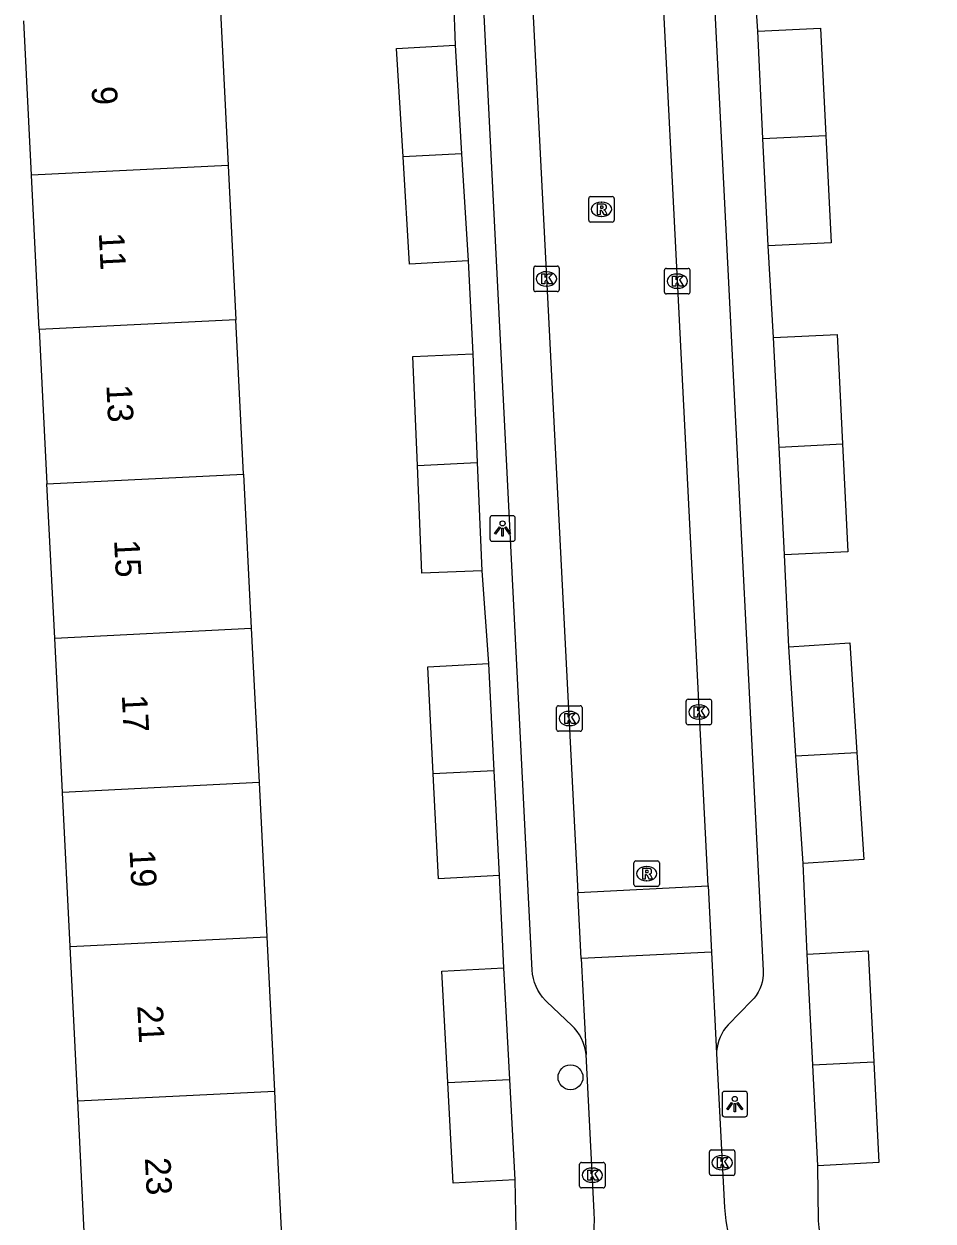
# Model space of a CAD drawing. Extents: x 161084 to 161928, y 385355 to 386522.
# Drawn here: x 161437.71 to 161473.38, y 385662.25 to 385709.2 of the extents above; entities that cross this region are included whole.
import ezdxf

# ---------------------------------------------------------------- set-up
doc = ezdxf.new("R2010")
doc.units = 0
for name, color, linetype in [('IMGEO_Boom', 7, 'Continuous'), ('IMGEO_Kolk', 7, 'Continuous'), ('IMGEO_Lichtpunt', 7, 'Continuous'), ('IMGEO_Pand', 7, 'Continuous'), ('IMGEO_Pand_nummerreeks', 7, 'Continuous'), ('IMGEO_Rijbaan_lokaal_open', 7, 'Continuous'), ('IMGEO_Rioolput', 7, 'Continuous'), ('IMGEO_Voetpad_open', 7, 'Continuous')]:
    doc.layers.add(name, color=color, linetype=linetype)

msp = doc.modelspace()

# ---------------------------------------------------------------- linework, layer by layer
at = {"layer": 'IMGEO_Boom'}
msp.add_circle((161459.156, 385667.888), 0.489, dxfattribs=at)
at = {"layer": 'IMGEO_Kolk'}
for p, q in [((161457.711, 385698.777), (161457.711, 385699.629)), ((161457.786, 385699.703), (161458.638, 385699.703)), ((161458.199, 385699.483), (161458.224, 385699.483)), ((161458.712, 385699.629), (161458.712, 385698.777)), ((161462.843, 385698.687), (161462.843, 385699.539)), ((161462.918, 385699.613), (161463.77, 385699.613)), ((161463.331, 385699.393), (161463.356, 385699.393)), ((161463.844, 385699.539), (161463.844, 385698.687)), ((161458.222, 385698.923), (161458.197, 385698.923)), ((161463.354, 385698.833), (161463.329, 385698.833)), ((161458.638, 385698.703), (161457.786, 385698.703)), ((161463.77, 385698.613), (161462.918, 385698.613)), ((161458.606, 385681.534), (161458.606, 385682.386)), ((161458.681, 385682.46), (161459.533, 385682.46)), ((161459.607, 385682.386), (161459.607, 385681.534)), ((161463.693, 385681.79), (161463.693, 385682.642)), ((161463.768, 385682.716), (161464.62, 385682.716)), ((161464.181, 385682.496), (161464.206, 385682.496)), ((161464.694, 385682.642), (161464.694, 385681.79)), ((161459.094, 385682.24), (161459.119, 385682.24)), ((161464.204, 385681.936), (161464.179, 385681.936)), ((161459.533, 385681.46), (161458.681, 385681.46)), ((161459.117, 385681.68), (161459.092, 385681.68)), ((161464.62, 385681.716), (161463.768, 385681.716)), ((161464.681, 385665.041), (161465.533, 385665.041)), ((161459.587, 385664.549), (161460.439, 385664.549)), ((161464.606, 385664.115), (161464.606, 385664.967)), ((161465.094, 385664.821), (161465.119, 385664.821)), ((161465.607, 385664.967), (161465.607, 385664.115)), ((161459.512, 385663.623), (161459.512, 385664.475)), ((161460, 385664.329), (161460.025, 385664.329)), ((161460.513, 385664.475), (161460.513, 385663.623)), ((161465.533, 385664.041), (161464.681, 385664.041)), ((161465.117, 385664.261), (161465.092, 385664.261)), ((161460.023, 385663.769), (161459.998, 385663.769)), ((161460.439, 385663.549), (161459.587, 385663.549))]:
    msp.add_line(p, q, dxfattribs=at)
for points in [[(161457.711, 385698.777), (161457.711, 385699.629)], [(161457.786, 385699.703), (161458.638, 385699.703)], [(161458.032, 385699.403), (161458.155, 385699.403), (161458.155, 385699.252), (161458.285, 385699.403), (161458.449, 385699.403), (161458.303, 385699.252), (161458.456, 385699.003), (161458.304, 385699.003), (161458.219, 385699.167), (161458.155, 385699.1), (161458.155, 385699.003), (161458.032, 385699.003), (161458.032, 385699.403)], [(161458.712, 385699.629), (161458.712, 385698.777)], [(161462.843, 385698.687), (161462.843, 385699.539)], [(161462.918, 385699.613), (161463.77, 385699.613)], [(161463.164, 385699.313), (161463.287, 385699.313), (161463.287, 385699.162), (161463.417, 385699.313), (161463.581, 385699.313), (161463.435, 385699.162), (161463.588, 385698.913), (161463.436, 385698.913), (161463.351, 385699.077), (161463.287, 385699.01), (161463.287, 385698.913), (161463.164, 385698.913), (161463.164, 385699.313)], [(161463.844, 385699.539), (161463.844, 385698.687)], [(161458.638, 385698.703), (161457.786, 385698.703)], [(161463.77, 385698.613), (161462.918, 385698.613)], [(161458.606, 385681.534), (161458.606, 385682.386)], [(161458.681, 385682.46), (161459.533, 385682.46)], [(161459.607, 385682.386), (161459.607, 385681.534)], [(161463.693, 385681.79), (161463.693, 385682.642)], [(161463.768, 385682.716), (161464.62, 385682.716)], [(161464.014, 385682.416), (161464.137, 385682.416), (161464.137, 385682.265), (161464.267, 385682.416), (161464.431, 385682.416), (161464.285, 385682.265), (161464.438, 385682.016), (161464.286, 385682.016), (161464.201, 385682.18), (161464.137, 385682.113), (161464.137, 385682.016), (161464.014, 385682.016), (161464.014, 385682.416)], [(161464.694, 385682.642), (161464.694, 385681.79)], [(161458.927, 385682.16), (161459.05, 385682.16), (161459.05, 385682.009), (161459.18, 385682.16), (161459.344, 385682.16), (161459.198, 385682.009), (161459.351, 385681.76), (161459.199, 385681.76), (161459.114, 385681.924), (161459.05, 385681.857), (161459.05, 385681.76), (161458.927, 385681.76), (161458.927, 385682.16)], [(161459.533, 385681.46), (161458.681, 385681.46)], [(161464.62, 385681.716), (161463.768, 385681.716)], [(161464.681, 385665.041), (161465.533, 385665.041)], [(161459.587, 385664.549), (161460.439, 385664.549)], [(161464.606, 385664.115), (161464.606, 385664.967)], [(161464.927, 385664.741), (161465.05, 385664.741), (161465.05, 385664.59), (161465.18, 385664.741), (161465.344, 385664.741), (161465.198, 385664.59), (161465.351, 385664.341), (161465.199, 385664.341), (161465.114, 385664.505), (161465.05, 385664.438), (161465.05, 385664.341), (161464.927, 385664.341), (161464.927, 385664.741)], [(161465.607, 385664.967), (161465.607, 385664.115)], [(161459.512, 385663.623), (161459.512, 385664.475)], [(161459.833, 385664.249), (161459.956, 385664.249), (161459.956, 385664.098), (161460.086, 385664.249), (161460.25, 385664.249), (161460.104, 385664.098), (161460.257, 385663.849), (161460.105, 385663.849), (161460.02, 385664.013), (161459.956, 385663.946), (161459.956, 385663.849), (161459.833, 385663.849), (161459.833, 385664.249)], [(161460.513, 385664.475), (161460.513, 385663.623)], [(161465.533, 385664.041), (161464.681, 385664.041)], [(161460.439, 385663.549), (161459.587, 385663.549)]]:
    msp.add_lwpolyline(points, dxfattribs=at)
for centre, start, end in [((161457.788, 385699.627), 91.552, 178.448), ((161457.788, 385699.627), 91.552, 178.448), ((161458.636, 385699.627), 1.552, 88.448), ((161458.636, 385699.627), 1.552, 88.448), ((161462.92, 385699.537), 91.552, 178.448), ((161462.92, 385699.537), 91.552, 178.448), ((161463.768, 385699.537), 1.552, 88.448), ((161463.768, 385699.537), 1.552, 88.448), ((161457.788, 385698.779), 181.552, 268.448), ((161457.788, 385698.779), 181.552, 268.448), ((161458.636, 385698.779), 271.552, 358.448), ((161458.636, 385698.779), 271.552, 358.448), ((161462.92, 385698.689), 181.552, 268.448), ((161462.92, 385698.689), 181.552, 268.448), ((161463.768, 385698.689), 271.552, 358.448), ((161463.768, 385698.689), 271.552, 358.448), ((161458.683, 385682.384), 91.552, 178.448), ((161458.683, 385682.384), 91.552, 178.448), ((161459.531, 385682.384), 1.552, 88.448), ((161459.531, 385682.384), 1.552, 88.448), ((161463.77, 385682.64), 91.552, 178.448), ((161463.77, 385682.64), 91.552, 178.448), ((161464.618, 385682.64), 1.552, 88.448), ((161464.618, 385682.64), 1.552, 88.448), ((161458.683, 385681.536), 181.552, 268.448), ((161458.683, 385681.536), 181.552, 268.448), ((161459.531, 385681.536), 271.552, 358.448), ((161459.531, 385681.536), 271.552, 358.448), ((161463.77, 385681.792), 181.552, 268.448), ((161463.77, 385681.792), 181.552, 268.448), ((161464.618, 385681.792), 271.552, 358.448), ((161464.618, 385681.792), 271.552, 358.448), ((161464.683, 385664.965), 91.552, 178.448), ((161464.683, 385664.965), 91.552, 178.448), ((161465.531, 385664.965), 1.552, 88.448), ((161465.531, 385664.965), 1.552, 88.448), ((161459.589, 385664.473), 91.552, 178.448), ((161459.589, 385664.473), 91.552, 178.448), ((161460.437, 385664.473), 1.552, 88.448), ((161460.437, 385664.473), 1.552, 88.448), ((161464.683, 385664.117), 181.552, 268.448), ((161464.683, 385664.117), 181.552, 268.448), ((161465.531, 385664.117), 271.552, 358.448), ((161465.531, 385664.117), 271.552, 358.448), ((161459.589, 385663.625), 181.552, 268.448), ((161459.589, 385663.625), 181.552, 268.448), ((161460.437, 385663.625), 271.552, 358.448), ((161460.437, 385663.625), 271.552, 358.448)]:
    msp.add_arc(centre, 0.0765, start, end, dxfattribs=at)
for centre, major_axis, ratio, start_param, end_param in [((161458.198, 385699.203), (-0.387, 0.002), 0.722429, 4.712389, 7.853982), ((161458.223, 385699.203), (-0.39, 0.002), 0.717154, 1.570796, 4.712389), ((161463.33, 385699.113), (-0.387, 0.002), 0.722429, 4.712389, 7.853982), ((161463.355, 385699.113), (-0.39, 0.002), 0.717154, 1.570796, 4.712389), ((161464.18, 385682.216), (-0.387, 0.002), 0.722429, 4.712389, 7.853982), ((161464.205, 385682.216), (-0.39, 0.002), 0.717154, 1.570796, 4.712389), ((161459.093, 385681.96), (-0.387, 0.002), 0.722429, 4.712389, 7.853982), ((161459.118, 385681.96), (-0.39, 0.002), 0.717154, 1.570796, 4.712389), ((161465.093, 385664.541), (-0.387, 0.002), 0.722429, 4.712389, 7.853982), ((161465.118, 385664.541), (-0.39, 0.002), 0.717154, 1.570796, 4.712389), ((161459.999, 385664.049), (-0.387, 0.002), 0.722429, 4.712389, 7.853982), ((161460.024, 385664.049), (-0.39, 0.002), 0.717154, 1.570796, 4.712389)]:
    msp.add_ellipse(centre, major_axis=major_axis, ratio=ratio, start_param=start_param, end_param=end_param, dxfattribs=at)
at = {"layer": 'IMGEO_Lichtpunt'}
for p, q in [((161456.893, 385689.911), (161456.085, 385689.911)), ((161456.893, 385689.911), (161456.085, 385689.911)), ((161455.991, 385689.816), (161455.991, 385689.009)), ((161455.991, 385689.816), (161455.991, 385689.009)), ((161456.987, 385689.009), (161456.987, 385689.816)), ((161456.987, 385689.009), (161456.987, 385689.816)), ((161456.085, 385688.915), (161456.893, 385688.915)), ((161456.085, 385688.915), (161456.893, 385688.915)), ((161466.004, 385667.337), (161465.196, 385667.337)), ((161466.004, 385667.337), (161465.196, 385667.337)), ((161465.102, 385667.242), (161465.102, 385666.435)), ((161465.102, 385667.242), (161465.102, 385666.435)), ((161466.098, 385666.435), (161466.098, 385667.242)), ((161466.098, 385666.435), (161466.098, 385667.242)), ((161465.196, 385666.341), (161466.004, 385666.341)), ((161465.196, 385666.341), (161466.004, 385666.341))]:
    msp.add_line(p, q, dxfattribs=at)
for points in [[(161456.365, 385689.48), (161456.404, 385689.452), (161456.216, 385689.19), (161456.178, 385689.217), (161456.365, 385689.48)], [(161456.467, 385689.432), (161456.514, 385689.432), (161456.514, 385689.11), (161456.467, 385689.11), (161456.467, 385689.432)], [(161456.577, 385689.452), (161456.615, 385689.479), (161456.802, 385689.217), (161456.763, 385689.189), (161456.577, 385689.452)], [(161465.476, 385666.906), (161465.515, 385666.878), (161465.327, 385666.616), (161465.289, 385666.643), (161465.476, 385666.906)], [(161465.578, 385666.858), (161465.625, 385666.858), (161465.625, 385666.536), (161465.578, 385666.536), (161465.578, 385666.858)], [(161465.688, 385666.878), (161465.726, 385666.905), (161465.913, 385666.643), (161465.874, 385666.615), (161465.688, 385666.878)]]:
    msp.add_lwpolyline(points, dxfattribs=at)
for centre in [(161456.49, 385689.614), (161465.601, 385667.04)]:
    msp.add_circle(centre, 0.0994, dxfattribs=at)
for centre, start, end in [((161456.085, 385689.816), 90, 180), ((161456.085, 385689.816), 90, 180), ((161456.893, 385689.816), 0, 90), ((161456.893, 385689.816), 0, 90), ((161456.085, 385689.009), 180, 270), ((161456.085, 385689.009), 180, 270), ((161456.893, 385689.009), 270, 0), ((161456.893, 385689.009), 270, 360), ((161465.196, 385667.242), 90, 180), ((161465.196, 385667.242), 90, 180), ((161466.004, 385667.242), 0, 90), ((161466.004, 385667.242), 0, 90), ((161465.196, 385666.435), 180, 270), ((161465.196, 385666.435), 180, 270), ((161466.004, 385666.435), 270, 0), ((161466.004, 385666.435), 270, 360)]:
    msp.add_arc(centre, 0.0946, start, end, dxfattribs=at)
at = {"layer": 'IMGEO_Pand'}
for points in [[(161445.425, 385709.704), (161445.727, 385703.653)], [(161438.012, 385703.269), (161437.711, 385709.32)], [(161466.502, 385708.921), (161468.969, 385709.041), (161469.174, 385704.83)], [(161466.707, 385704.704), (161466.502, 385708.921)], [(161452.585, 385703.994), (161452.333, 385708.233), (161454.631, 385708.369)], [(161454.631, 385708.369), (161454.884, 385704.109)], [(161466.707, 385704.704), (161469.174, 385704.83)], [(161466.912, 385700.497), (161466.707, 385704.704)], [(161469.174, 385704.83), (161469.379, 385700.617), (161466.912, 385700.497)], [(161454.884, 385704.109), (161452.585, 385703.994)], [(161455.134, 385699.91), (161452.836, 385699.774), (161452.585, 385703.994)], [(161454.884, 385704.109), (161455.134, 385699.91)], [(161445.727, 385703.653), (161438.012, 385703.269)], [(161445.727, 385703.653), (161446.029, 385697.602)], [(161438.314, 385697.218), (161438.012, 385703.269)], [(161446.029, 385697.602), (161438.314, 385697.218)], [(161446.331, 385691.55), (161446.029, 385697.602)], [(161438.314, 385697.218), (161438.616, 385691.166)], [(161467.126, 385696.903), (161469.617, 385697.026), (161469.83, 385692.727)], [(161467.339, 385692.6), (161467.126, 385696.903)], [(161453.147, 385691.889), (161452.97, 385696.164), (161455.322, 385696.261)], [(161455.322, 385696.261), (161455.498, 385692.006)], [(161467.339, 385692.6), (161469.83, 385692.727)], [(161469.83, 385692.727), (161470.039, 385688.5), (161467.548, 385688.377)], [(161467.548, 385688.377), (161467.339, 385692.6)], [(161453.147, 385691.889), (161455.498, 385692.006)], [(161455.674, 385687.755), (161453.322, 385687.658), (161453.147, 385691.889)], [(161455.498, 385692.006), (161455.674, 385687.755)], [(161438.616, 385691.166), (161446.331, 385691.55)], [(161446.331, 385691.55), (161446.632, 385685.499)], [(161438.917, 385685.115), (161438.616, 385691.166)], [(161438.917, 385685.115), (161446.632, 385685.499)], [(161446.632, 385685.499), (161446.934, 385679.447)], [(161439.219, 385679.063), (161438.917, 385685.115)], [(161467.724, 385684.765), (161470.114, 385684.922), (161470.396, 385680.623)], [(161468.003, 385680.501), (161467.724, 385684.765)], [(161453.767, 385679.787), (161453.555, 385683.992), (161455.934, 385684.112)], [(161455.934, 385684.112), (161456.146, 385679.906)], [(161468.003, 385680.501), (161470.396, 385680.623)], [(161468.279, 385676.277), (161468.003, 385680.501)], [(161470.396, 385680.623), (161470.67, 385676.433), (161468.279, 385676.277)], [(161456.146, 385679.906), (161453.767, 385679.787)], [(161456.353, 385675.798), (161453.974, 385675.678), (161453.767, 385679.787)], [(161456.146, 385679.906), (161456.353, 385675.798)], [(161446.934, 385679.447), (161439.219, 385679.063)], [(161439.521, 385673.012), (161439.219, 385679.063)], [(161446.934, 385679.447), (161447.236, 385673.396)], [(161439.521, 385673.012), (161447.236, 385673.396)], [(161439.823, 385666.96), (161439.521, 385673.012)], [(161447.236, 385673.396), (161447.538, 385667.344)], [(161468.441, 385672.721), (161470.839, 385672.842), (161471.058, 385668.497)], [(161468.66, 385668.371), (161468.441, 385672.721)], [(161454.341, 385667.683), (161454.111, 385672.055), (161456.529, 385672.182)], [(161456.529, 385672.182), (161456.76, 385667.803)], [(161468.66, 385668.371), (161471.058, 385668.497)], [(161468.859, 385664.422), (161468.66, 385668.371)], [(161471.058, 385668.497), (161471.257, 385664.543), (161468.859, 385664.422)], [(161454.341, 385667.683), (161456.76, 385667.803)], [(161456.76, 385667.803), (161456.968, 385663.862)], [(161447.538, 385667.344), (161447.599, 385666.114), (161447.848, 385661.12), (161440.133, 385660.736), (161439.823, 385666.96)], [(161439.823, 385666.96), (161447.538, 385667.344)], [(161456.968, 385663.862), (161454.549, 385663.734), (161454.341, 385667.683)]]:
    msp.add_lwpolyline(points, dxfattribs=at)
at = {"layer": 'IMGEO_Rijbaan_lokaal_open'}
for points in [[(161464.554, 385675.399), (161461.556, 385734.509)], [(161456.469, 385733.372), (161459.446, 385675.139)], [(161459.446, 385675.139), (161464.554, 385675.399)], [(161464.554, 385675.399), (161464.686, 385672.802)], [(161459.579, 385672.542), (161459.446, 385675.139)], [(161464.686, 385672.802), (161459.579, 385672.542)], [(161459.579, 385672.542), (161459.771, 385668.777)], [(161464.686, 385672.802), (161464.888, 385668.818)], [(161457.453, 385657.375), (161457.88, 385657.686), (161458.277, 385658.034), (161458.641, 385658.416), (161458.97, 385658.83), (161459.261, 385659.271), (161459.511, 385659.736), (161459.718, 385660.221), (161459.881, 385660.724), (161459.999, 385661.238), (161460.07, 385661.762), (161460.095, 385662.289), (161460.087, 385662.596), (161459.771, 385668.777)], [(161464.888, 385668.818), (161465.196, 385662.776), (161465.246, 385662.255), (161465.343, 385661.741), (161465.485, 385661.237), (161465.672, 385660.748), (161465.902, 385660.277), (161466.173, 385659.829), (161466.482, 385659.407), (161466.828, 385659.015), (161467.208, 385658.655), (161467.619, 385658.33), (161468.057, 385658.043), (161468.518, 385657.797), (161469, 385657.592), (161469.499, 385657.432), (161470.009, 385657.317), (161470.528, 385657.247), (161471.051, 385657.225), (161471.421, 385657.237), (161472.776, 385657.326)]]:
    msp.add_lwpolyline(points, dxfattribs=at)
at = {"layer": 'IMGEO_Rioolput'}
for p, q in [((161459.869, 385701.506), (161459.869, 385702.358)), ((161459.944, 385702.432), (161460.796, 385702.432)), ((161460.357, 385702.212), (161460.382, 385702.212)), ((161460.87, 385702.358), (161460.87, 385701.506)), ((161460.38, 385701.652), (161460.355, 385701.652)), ((161460.796, 385701.432), (161459.944, 385701.432)), ((161461.643, 385675.451), (161461.643, 385676.303)), ((161461.718, 385676.377), (161462.57, 385676.377)), ((161462.644, 385676.303), (161462.644, 385675.451)), ((161462.131, 385676.157), (161462.156, 385676.157)), ((161462.57, 385675.377), (161461.718, 385675.377)), ((161462.154, 385675.597), (161462.129, 385675.597))]:
    msp.add_line(p, q, dxfattribs=at)
for points in [[(161459.869, 385701.506), (161459.869, 385702.358)], [(161459.944, 385702.432), (161460.796, 385702.432)], [(161460.458, 385702.13), (161460.206, 385702.132), (161460.206, 385701.732)], [(161460.87, 385702.358), (161460.87, 385701.506)], [(161460.206, 385701.732), (161460.33, 385701.732), (161460.33, 385701.894), (161460.341, 385701.894)], [(161460.384, 385702.051), (161460.33, 385702.051), (161460.33, 385701.97)], [(161460.33, 385701.97), (161460.382, 385701.97)], [(161460.388, 385701.865), (161460.459, 385701.732), (161460.599, 385701.732), (161460.534, 385701.858)], [(161460.796, 385701.432), (161459.944, 385701.432)], [(161461.643, 385675.451), (161461.643, 385676.303)], [(161461.718, 385676.377), (161462.57, 385676.377)], [(161462.644, 385676.303), (161462.644, 385675.451)], [(161462.232, 385676.075), (161461.98, 385676.077), (161461.98, 385675.677)], [(161461.98, 385675.677), (161462.104, 385675.677), (161462.104, 385675.839), (161462.115, 385675.839)], [(161462.158, 385675.996), (161462.104, 385675.996), (161462.104, 385675.915)], [(161462.104, 385675.915), (161462.156, 385675.915)], [(161462.162, 385675.81), (161462.233, 385675.677), (161462.373, 385675.677), (161462.308, 385675.803)], [(161462.57, 385675.377), (161461.718, 385675.377)]]:
    msp.add_lwpolyline(points, dxfattribs=at)
for centre, radius, start, end in [((161459.946, 385702.356), 0.0765, 91.552, 178.448), ((161459.946, 385702.356), 0.0765, 91.552, 178.448), ((161460.457, 385702.02), 0.109, 350.3612, 89.416), ((161460.794, 385702.356), 0.0765, 1.552, 88.448), ((161460.794, 385702.356), 0.0765, 1.552, 88.448), ((161460.34, 385701.841), 0.0533, 26.0293, 88.6989), ((161460.366, 385702.159), 0.19, 274.7715, 282.9687), ((161460.39, 385701.955), 0.0964, 77.0061, 93.1865), ((161460.404, 385702.012), 0.0378, 276.6634, 79.6772), ((161460.455, 385702.02), 0.112, 277.5842, 350.9817), ((161460.439, 385701.805), 0.108, 29.5134, 73.7905), ((161459.946, 385701.508), 0.0765, 181.552, 268.448), ((161459.946, 385701.508), 0.0765, 181.552, 268.448), ((161460.794, 385701.508), 0.0765, 271.552, 358.448), ((161460.794, 385701.508), 0.0765, 271.552, 358.448), ((161461.72, 385676.301), 0.0765, 91.552, 178.448), ((161461.72, 385676.301), 0.0765, 91.552, 178.448), ((161462.568, 385676.301), 0.0765, 1.552, 88.448), ((161462.568, 385676.301), 0.0765, 1.552, 88.448), ((161462.114, 385675.786), 0.0533, 26.0293, 88.6989), ((161462.14, 385676.104), 0.19, 274.7715, 282.9687), ((161462.164, 385675.9), 0.0964, 77.0061, 93.1865), ((161462.178, 385675.957), 0.0378, 276.6634, 79.6772), ((161462.231, 385675.965), 0.109, 350.3612, 89.416), ((161462.229, 385675.965), 0.112, 277.5842, 350.9817), ((161462.213, 385675.75), 0.108, 29.5134, 73.7905), ((161461.72, 385675.453), 0.0765, 181.552, 268.448), ((161461.72, 385675.453), 0.0765, 181.552, 268.448), ((161462.568, 385675.453), 0.0765, 271.552, 358.448), ((161462.568, 385675.453), 0.0765, 271.552, 358.448)]:
    msp.add_arc(centre, radius, start, end, dxfattribs=at)
for centre, major_axis, ratio, start_param, end_param in [((161460.356, 385701.932), (-0.387, 0.002), 0.722429, 4.712389, 7.853982), ((161460.381, 385701.932), (-0.39, 0.002), 0.717154, 1.570796, 4.712389), ((161462.13, 385675.877), (-0.387, 0.002), 0.722429, 4.712389, 7.853982), ((161462.155, 385675.877), (-0.39, 0.002), 0.717154, 1.570796, 4.712389)]:
    msp.add_ellipse(centre, major_axis=major_axis, ratio=ratio, start_param=start_param, end_param=end_param, dxfattribs=at)
at = {"layer": 'IMGEO_Voetpad_open'}
for points in [[(161463.756, 385730.718), (161466.716, 385672.081), (161466.717, 385672.049), (161466.715, 385671.906), (161466.7, 385671.764), (161466.673, 385671.623), (161466.633, 385671.486), (161466.581, 385671.353), (161466.517, 385671.225), (161466.442, 385671.103), (161466.356, 385670.989), (161466.261, 385670.882), (161465.344, 385669.944), (161465.248, 385669.836), (161465.162, 385669.72), (161465.087, 385669.596), (161465.023, 385669.466), (161464.971, 385669.331), (161464.932, 385669.192), (161464.905, 385669.051), (161464.89, 385668.907), (161464.888, 385668.818)], [(161459.771, 385668.777), (161459.747, 385668.94), (161459.708, 385669.1), (161459.655, 385669.256), (161459.588, 385669.406), (161459.508, 385669.55), (161459.415, 385669.687), (161459.311, 385669.814), (161459.203, 385669.925), (161458.231, 385670.844), (161458.171, 385670.903), (161458.061, 385671.028), (161457.963, 385671.161), (161457.878, 385671.303), (161457.805, 385671.452), (161457.746, 385671.607), (161457.701, 385671.767), (161457.67, 385671.93), (161457.654, 385672.095), (161454.753, 385729.847)], [(161466.502, 385708.921), (161466.261, 385712.614)], [(161454.5, 385711.992), (161454.631, 385708.369)], [(161467.126, 385696.903), (161466.912, 385700.497)], [(161455.134, 385699.91), (161455.322, 385696.261)], [(161467.724, 385684.765), (161467.548, 385688.377)], [(161455.674, 385687.755), (161455.934, 385684.112)], [(161468.441, 385672.721), (161468.279, 385676.277)], [(161456.353, 385675.798), (161456.529, 385672.182)], [(161489.589, 385660.528), (161489.33, 385660.501), (161479.748, 385659.941), (161471.954, 385659.486), (161471.765, 385659.481), (161471.506, 385659.495), (161471.249, 385659.531), (161470.996, 385659.591), (161470.75, 385659.672), (161470.512, 385659.776), (161470.285, 385659.9), (161470.069, 385660.044), (161469.867, 385660.207), (161469.68, 385660.387), (161469.511, 385660.583), (161469.359, 385660.794), (161469.227, 385661.017), (161469.115, 385661.251), (161469.025, 385661.494), (161468.956, 385661.744), (161468.911, 385662), (161468.888, 385662.258), (161468.859, 385664.422)], [(161456.968, 385663.862), (161457.024, 385661.247), (161457.026, 385661.142)]]:
    msp.add_lwpolyline(points, dxfattribs=at)

# ---------------------------------------------------------------- texts
at = {"layer": 'IMGEO_Pand_nummerreeks'}
for s, p in [('9', (161440.362, 385706.738)), ('11', (161440.648, 385701.004)), ('13', (161440.945, 385695.037)), ('15', (161441.248, 385688.957)), ('17', (161441.551, 385682.877)), ('19', (161441.854, 385676.797)), ('21', (161442.16, 385670.695)), ('23', (161442.457, 385664.727))]:
    msp.add_text(s, height=1, rotation=272.8545, dxfattribs=at).set_placement(p)

doc.saveas('drawing.dxf')
